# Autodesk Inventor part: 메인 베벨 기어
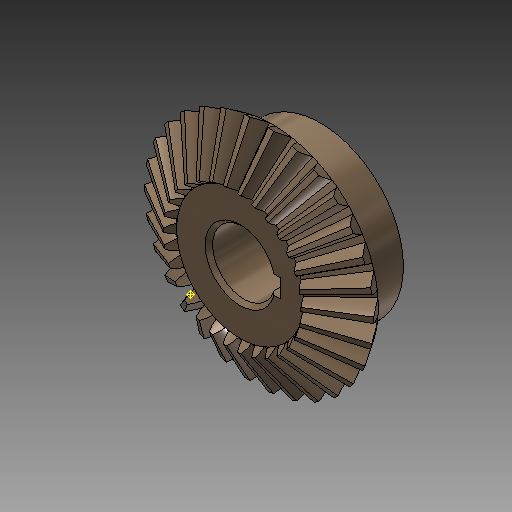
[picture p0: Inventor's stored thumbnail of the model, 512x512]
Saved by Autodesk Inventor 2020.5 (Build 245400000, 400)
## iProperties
CustomPartVersion: 1
Created: 2016-04
Part Number: 메인 베벨 기어
Material: 강철, 탄소
Document SubType Name: Modeling
Designer: mdu
Categories: <?xml version="1.0" encoding="UTF-16"?> <MemberInstance><Categories><FamilyTemplate><FamilyTemplateParameter ValueType="xs:double" Id="1" ObjectReferenceKey="da
Mass: 269.926 g
Surface Area: 108.837 cm^2
Volume: 34.2981 cm^3
Density: 7.87 g/cm^3
Appearance: 얼룩무늬
Author: mdu
Revision Number: 1
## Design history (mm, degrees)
node "맨 위 점"
node "메쉬 평면2"
sketch "톱니 본체 스케치"
  geometry: L1 (0, 0)-(28.669, -21.997); L2 (28.669, -21.997)-(31.109, -18.336); L3 (31.109, -18.336)-(0, 0); L4 (30, -20)-(0, 0); L5 (17.219, -13.212)-(18.685, -11.013); L6 (28.669, -21.997)-(17.219, -13.212); L7 (31.109, -18.336)-(18.685, -11.013); L8 (0, -39.387)-(0, 6.564) reference; L9 (0, -20)-(31.109, -20)
  constraints: 16 end point, 4 point on line, 3 perpendicular, 2 collinear, 1 horizontal alignment, 1 vertical alignment
  dimensions: "d0" = 60 diameter of L4.start L8 (= da_de); "d1" = 57.33744 diameter of L1.end L8 (= da_dfe); "d2" = 62.2188 diameter of L2.end L8 (= da_dae); "d3" = 14.4 distance between parallel lines of L2 L5 (= da_b); "d4" = 18.3359 vertical distance of L2.end L1.start (= da_ve)
revolve "톱니 본체" sketch "톱니 본체 스케치" stored, may be unused: angle "d5" = 90 deg
node "시작점"
node "톱니 평면"
sketch "시작 스케치"
  geometry: L1 (0, -23.505)-(0, 10.645) reference; L2 (-0.709, -2.928)-(0.709, -2.928); A1 r 19.188 centre (-19.457, -7.014) between (-0.709, -2.928) and (-3.232, 3.229); A2 r 19.188 centre (19.457, -7.014) between (3.232, 3.229) and (0.709, -2.928); A3 r 57.403 centre (0, -54.083) between (3.232, 3.229) and (-3.232, 3.229); 1 further point
  constraints: 6 point on circle, 3 centre point, 3 symmetric about line, 2 end point, 1 coincident, 1 perpendicular, 1 other
  dimensions: "d7" = 19.18795 radius of A1 (= fd_rr); "d8" = 19.45712 horizontal distance of point (0, -54.083) A1.centre (= fd_x); "d9" = 47.06905 vertical distance of point (0, -54.083) A1.centre (= fd_y); "d57" = 57.40327 radius of A3 (= 0.5 x fd_dva + 0.3 x da_he); "d58" = 51.15527 distance from line of A3.centre L2 (= 0.5 x fd_dva - 1.12 x da_he)
node "끝점"
  node "끝 평면"
sketch "3D 스케치 오른쪽"
  node "Helical Curve Right" dims "d65" = 229.90621 (computed from da_dm, da_delta, da_beta), "d66" = 31.5, "d67" = 60 (= da_de), "d68" = -9.82794 (= -da_delta), "d69" = 8.10972 (computed from fd_loft, da_delta)
node "끝 평면 오른쪽"
sketch "끝 스케치 오른쪽"
  geometry: L1 (0, -41.54)-(0, 13.178) reference; L2 (-0.422, -1.69)-(0.422, -1.69); A1 r 11.427 centre (-11.587, -4.123) between (-0.422, -1.69) and (-1.925, 1.977); A2 r 11.427 centre (11.587, -4.123) between (1.925, 1.977) and (0.422, -1.69); A3 r 34.184 centre (0, -32.153) between (1.925, 1.977) and (-1.925, 1.977); 1 further point
  constraints: 6 point on circle, 3 centre point, 3 symmetric about line, 2 end point, 1 coincident, 1 perpendicular, 1 other
  dimensions: "d70" = 11.58699 horizontal distance of A3.centre A1.centre (computed from fd_x, fd_ratio); "d71" = 28.03028 vertical distance of point (0, -32.153) A1.centre (computed from fd_y, fd_ratio); "d72" = 11.4267 radius of A1 (computed from fd_rr, fd_ratio); "d73" = 30.46369 distance from line of point (0, -32.153) L2 (computed from d58, fd_ratio); "d74" = 34.18446 radius of A3 (computed from d57, fd_ratio)
feature "로프트 오른쪽" sketch "끝 스케치 오른쪽" dims "d75" = 0, "d77" = 0, "d79" = 0, "d80" = 90 deg, "d85" = 20, "d92" = 90 deg, "d93" = 90 deg, "da_teethtype" = 0 [user parameter]
sketch "3D 스케치 왼쪽"
  node "Helical Curve Left" dims "d26" = 229.90621 (computed from da_dm, da_delta, da_beta), "d27" = 8.10972 (computed from fd_loft, da_delta), "d28" = 60 (= da_de), "d29" = -9.82794 (= -da_delta)
node "끝 평면 왼쪽"
sketch "끝 스케치 왼쪽" dims "d56" = 10.3728 (derived)
  geometry: L1 (0, -43.753)-(0, 15.405) reference; L2 (-0.422, -1.678)-(0.422, -1.678); A1 r 11.427 centre (-11.587, -4.111) between (-0.422, -1.678) and (-1.925, 1.988); A2 r 11.427 centre (11.587, -4.111) between (1.925, 1.988) and (0.422, -1.678); A3 r 34.184 centre (0, -32.142) between (1.925, 1.988) and (-1.925, 1.988); 2 further points; 1 other entity
  constraints: 6 point on circle, 3 centre point, 3 symmetric about line, 2 end point, 1 coincident, 2 other
  dimensions: "d30" = 11.4267 radius of A1 (computed from fd_rr, fd_ratio); "d31" = 11.58699 horizontal distance of point (0, -32.142) A1.centre (computed from fd_x, fd_ratio); "d32" = 28.03028 vertical distance of A1.centre point (0, -32.142) (computed from fd_y, fd_ratio); "d61" = 34.18446 radius of A3 (computed from d57, fd_ratio); "d62" = 30.46369 distance from line of point (0, -32.142) L2 (computed from d58, fd_ratio)
feature "로프트 왼쪽" sketch "끝 스케치 왼쪽" dims "d35" = 0, "d37" = 0, "d39" = 0, "d40" = 90 deg, "d84" = 10, "d90" = 90 deg, "d91" = 90 deg, "da_teethtype" = 0 [user parameter]
sketch "본체 스케치"
  geometry: L1 (0, -35.038)-(0, -19.531) reference; L2 (28.669, -21.997)-(17.219, -13.212) reference; L3 (17.219, -13.212)-(0, -13.212); L4 (28.669, -21.997)-(0, -21.997)
  constraints: 4 end point, 2 perpendicular, 2 point on line
revolve "본체 고정" sketch "본체 스케치" stored, may be unused: angle "d46" = 90 deg
feature "피치 지름" dims angle "d47" = 90 deg
sketch "스케치8"
  geometry: C1 r 22.5 at (0, 0); 1 further point
  constraints: 1 centre point, 1 coincident
  dimensions: "d94" = 45 diameter of C1
extrude "돌출1" join sketch "스케치8" distance "d95" = 13; taper "d96" = 0 deg
sketch "스케치9"
  geometry: 1 further point
hole "구멍1" sketch "스케치9" at (0, 0) diameter "d97" = 17; stored, may be unused: countersink angle "d101" = 90 deg, drill point angle "d103" = 118 deg; dims "d98" = 6, "d99" = 4, "d100" = 2, "d102" = 8
sketch "스케치10"
  geometry: L1 (8.124, 2.5)-(10.8, 2.5); L2 (10.8, 2.5)-(10.8, -2.5); L3 (10.8, -2.5)-(8.124, -2.5); A1 r 8.5 centre (0, 0) between (8.124, 2.5) and (8.124, -2.5) reference; 1 further point
  constraints: 6 end point, 2 parallel, 2 point on circle, 1 horizontal, 1 perpendicular
  dimensions: "d104" = 5 distance of L1.end L2.end; "d112" = 19.3 dimension on A1 L2
extrude "돌출2" cut sketch "스케치10" extent not by distance; stored distance "d106" = 10; taper "d107" = 0 deg
chamfer "모따기1" distance "d108" = 1; stored, may be unused: second distance "d109" = 2, angle "d110" = 45 deg
fillet "모깎기1" dims "d111" = 2
body "Solid1"
feature "로프트" dims "d17" = 0, "d18" = 90 deg, "d19" = 0, "d20" = 90 deg, "d89" = 0, "da_teethtype" = 0 [user parameter]
pattern_circular "원형 패턴" dims angle "d22" = 360 deg, "d88" = 0, "da_teethtype" = 0 [user parameter]
pattern_circular "원형 패턴 오른쪽" dims angle "d82" = 360 deg, "da_teethtype" = 0 [user parameter]
pattern_circular "원형 패턴 왼쪽" dims angle "d42" = 360 deg, "da_teethtype" = 0 [user parameter]
sketch "끝 스케치"
  geometry: L1 (0, -15.359)-(0, 6.983) reference; L2 (-0.422, -1.69)-(0.422, -1.69); A1 r 11.427 centre (-11.587, -4.123) between (-0.422, -1.69) and (-1.925, 1.977); A2 r 11.427 centre (11.587, -4.123) between (1.925, 1.977) and (0.422, -1.69); A3 r 34.184 centre (0, -32.153) between (1.925, 1.977) and (-1.925, 1.977); 1 further point
  constraints: 6 point on circle, 3 centre point, 3 symmetric about line, 2 end point, 1 coincident, 1 other
  dimensions: "d12" = 11.4267 radius of A1 (computed from fd_rr, fd_ratio); "d15" = 11.58699 horizontal distance of A1.centre point (0, -32.153) (computed from fd_x, fd_ratio); "d16" = 28.03028 vertical distance of A1.centre point (0, -32.153) (computed from fd_y, fd_ratio); "d59" = 34.18446 radius of A3 (computed from d57, fd_ratio); "d60" = 30.46369 distance from line of A3.centre L2 (computed from d58, fd_ratio)
sketch "Sketch6"
  geometry: L1 (30, -20)-(0, 0) reference; L2 (0, -37.8)-(0, 6.3) reference
body "Srf1"
other parameters: "da_b" = 14.4 [user parameter; used in 2 equation terms], "da_de" = 60 [user parameter; used in 4 equation terms], "da_dae" = 62.2188 [user parameter; used in 2 equation terms], "da_dfe" = 57.33744 [user parameter; used in 1 equation term], "da_le" = 36.05551 [user parameter; used in 1 equation term], "da_omega" = 90 deg [user parameter; used in 1 equation term], "da_beta" = 0 [user parameter; used in 2 equation terms], "da_delta" = 9.82794 [user parameter; used in 8 equation terms], "da_alpha" = 20 deg [user parameter; used in 2 equation terms], "da_he" = 4.4 [user parameter; used in 4 equation terms], "da_ve" = 18.3359 [user parameter; used in 1 equation term], "fd_dv" = 108.16654 (computed from da_de, da_delta) [user parameter; used in 1 equation term], "fd_dva" = 112.16654 (computed from da_dae, da_delta) [user parameter; used in 3 equation terms], "fd_dvb" = 101.6433 (computed from fd_dv, da_alpha) [user parameter; used in 2 equation terms], "da_zv" = 540.83269 [user parameter; used in 1 equation term], "fd_loft" = 14.62 (= da_b + 0.05 x da_he) [user parameter; used in 4 equation terms], "fd_ratio" = 5.95514 (computed from da_le, fd_loft) [user parameter; used in 15 equation terms], "fd_rr" = 19.18795 (computed from fd_dd, fd_dvb) [user parameter; used in 6 equation terms], "fd_angle" = 0.29367 (computed from da_zv) [user parameter; used in 4 equation terms], "fd_x1" = 1.58802 (computed from da_dvw, fd_angle) [user parameter; used in 1 equation term], "fd_y1" = 54.05995 (computed from da_dvw, fd_angle) [user parameter; used in 1 equation term], "fd_x2" = 17.8691 (computed from fd_rr, fd_angle2, fd_angle) [user parameter; used in 1 equation term], "fd_y2" = 6.9909 (computed from fd_rr, fd_angle2, fd_angle) [user parameter; used in 1 equation term], "fd_x" = 19.45712 (= fd_x1 + fd_x2) [user parameter; used in 4 equation terms], "fd_y" = 47.06905 (= fd_y1 - fd_y2) [user parameter; used in 4 equation terms], "fd_angle2" = 3.43555 (computed from fd_dvb, fd_dd, da_alpha) [user parameter; used in 2 equation terms], "fd_dd" = 108.64654 (= fd_dva - 0.8 x da_he) [user parameter; used in 2 equation terms], "da_dvw" = 108.16654 [user parameter; used in 2 equation terms], "d11" = 14.62 (= fd_loft), "da_dm" = 48.01848 [user parameter; used in 2 equation terms], "da_x" = 0 [user parameter], "da_m" = 2 [user parameter], "d48" = 0, "d49" = 0, "d50" = 90 deg (= da_omega), "d51" = 6 deg (computed from da_z), "d52" = 0, "d53" = 0, "d54" = 0
